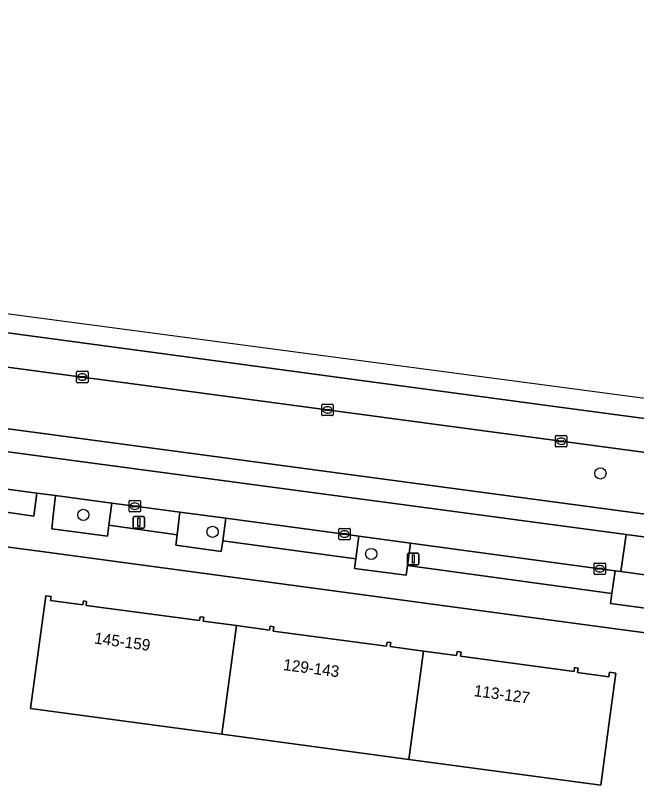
# Model space of a CAD drawing. Extents: x 161258 to 161838, y 380833 to 381727.
# Drawn here: x 161609.6 to 161663.8, y 381638.5 to 381706.2 of the extents above; entities that cross this region are included whole.
import ezdxf

# ---------------------------------------------------------------- set-up
doc = ezdxf.new("R2010")
doc.units = 0
for name, color, linetype in [('IMGEO_Berm_groen', 7, 'Continuous'), ('IMGEO_Boom', 7, 'Continuous'), ('IMGEO_Erf', 7, 'Continuous'), ('IMGEO_Groenvoorziening', 7, 'Continuous'), ('IMGEO_Kolk', 7, 'Continuous'), ('IMGEO_Lichtmast', 7, 'Continuous'), ('IMGEO_Pand', 7, 'Continuous'), ('IMGEO_Pand_nummerreeks', 7, 'Continuous'), ('IMGEO_Parkeervlak_halfverhard', 7, 'Continuous'), ('IMGEO_Parkeervlak_open', 7, 'Continuous'), ('IMGEO_Rijbaan_lokaal_open', 7, 'Continuous'), ('IMGEO_Rijbaan_regionaal_gesloten', 7, 'Continuous'), ('IMGEO_Voetpad_open', 7, 'Continuous')]:
    doc.layers.add(name, color=color, linetype=linetype)

msp = doc.modelspace()

# ---------------------------------------------------------------- linework, layer by layer
at = {"layer": 'IMGEO_Berm_groen'}
for points in [[(161419.518, 381699.804), (161598.175, 381675.897), (161597.877, 381673.07), (161595.231, 381672.953), (161593.354, 381672.734), (161591.581, 381672.404), (161665.053, 381662.56), (161687.397, 381659.556)], [(161679.007, 381666.04), (161677.666, 381666.255), (161657.266, 381668.988), (161618.127, 381674.239), (161615.451, 381674.598), (161596.053, 381677.191), (161575.643, 381679.932), (161555.208, 381682.652), (161534.802, 381685.416)]]:
    msp.add_lwpolyline(points, dxfattribs=at)
at = {"layer": 'IMGEO_Boom'}
for centre in [(161660.703, 381666.175), (161615.541, 381662.553), (161626.823, 381661.069), (161640.685, 381659.137)]:
    msp.add_circle(centre, 0.489, dxfattribs=at)
at = {"layer": 'IMGEO_Erf'}
msp.add_lwpolyline([(161744.895, 381638.467), (161745.302, 381641.497), (161740.472, 381642.131), (161716.743, 381645.239), (161684.01, 381649.696), (161663.105, 381652.447), (161611.247, 381659.449), (161599.202, 381661.023)], dxfattribs=at)
msp.add_lwpolyline([(161615.892, 381644.965), (161610.936, 381645.632), (161612.263, 381655.486), (161612.719, 381655.424), (161612.672, 381655.072), (161615.508, 381654.69), (161615.554, 381655.027), (161615.829, 381654.99), (161615.782, 381654.645), (161625.697, 381653.309), (161625.742, 381653.644), (161626.056, 381653.602), (161626.011, 381653.266), (161628.905, 381652.876), (161631.798, 381652.487), (161631.843, 381652.817), (161632.176, 381652.772), (161632.126, 381652.403), (161642.024, 381651.07), (161642.072, 381651.429), (161642.386, 381651.387), (161642.339, 381651.04), (161645.237, 381650.649), (161648.134, 381650.259), (161648.181, 381650.609), (161648.533, 381650.562), (161648.485, 381650.206), (161658.399, 381648.87), (161658.444, 381649.202), (161658.753, 381649.16), (161658.7, 381648.764), (161661.437, 381648.395), (161661.491, 381648.794), (161662.041, 381648.72), (161661.374, 381643.765), (161660.722, 381638.927), (161643.962, 381641.184), (161627.626, 381643.385)], close=True, dxfattribs=at)
at = {"layer": 'IMGEO_Groenvoorziening'}
for points in [[(161618.02, 381663.581), (161613.107, 381664.241), (161612.89, 381662.2), (161612.798, 381661.333), (161617.639, 381660.694), (161617.765, 381661.651)], [(161627.98, 381662.252), (161623.981, 381662.785), (161623.732, 381660.793), (161623.621, 381659.901), (161627.59, 381659.365), (161627.712, 381660.269)], [(161644.101, 381660.091), (161639.609, 381660.701), (161639.338, 381658.697), (161639.226, 381657.866), (161643.74, 381657.285), (161643.847, 381658.115)], [(161667.573, 381656.908), (161667.085, 381656.974), (161662.493, 381657.593), (161661.981, 381657.663), (161661.692, 381655.679), (161661.566, 381654.809), (161667.214, 381654.038), (161667.325, 381654.926)]]:
    msp.add_lwpolyline(points, close=True, dxfattribs=at)
at = {"layer": 'IMGEO_Kolk'}
for p, q in [((161614.95, 381674.17), (161614.95, 381675.022)), ((161615.025, 381675.096), (161615.877, 381675.096)), ((161615.438, 381674.876), (161615.463, 381674.876)), ((161615.951, 381675.022), (161615.951, 381674.17)), ((161615.877, 381674.096), (161615.025, 381674.096)), ((161615.209, 381674.59), (161615.209, 381674.602)), ((161615.647, 381674.553), (161615.249, 381674.553)), ((161615.252, 381674.639), (161615.65, 381674.639)), ((161615.461, 381674.316), (161615.436, 381674.316)), ((161615.693, 381674.602), (161615.693, 381674.59)), ((161636.358, 381671.299), (161636.358, 381672.151)), ((161636.433, 381672.225), (161637.285, 381672.225)), ((161636.846, 381672.005), (161636.871, 381672.005)), ((161637.359, 381672.151), (161637.359, 381671.299)), ((161636.617, 381671.719), (161636.617, 381671.731)), ((161637.055, 381671.682), (161636.657, 381671.682)), ((161636.66, 381671.768), (161637.058, 381671.768)), ((161636.869, 381671.445), (161636.844, 381671.445)), ((161637.101, 381671.731), (161637.101, 381671.719)), ((161637.285, 381671.225), (161636.433, 381671.225)), ((161656.765, 381668.561), (161656.765, 381669.413)), ((161656.84, 381669.487), (161657.692, 381669.487)), ((161657.766, 381669.413), (161657.766, 381668.561)), ((161657.024, 381668.981), (161657.024, 381668.993)), ((161657.462, 381668.944), (161657.064, 381668.944)), ((161657.067, 381669.03), (161657.465, 381669.03)), ((161657.276, 381668.707), (161657.251, 381668.707)), ((161657.253, 381669.267), (161657.278, 381669.267)), ((161657.508, 381668.993), (161657.508, 381668.981)), ((161657.692, 381668.487), (161656.84, 381668.487)), ((161619.532, 381662.884), (161619.532, 381663.736)), ((161619.607, 381663.81), (161620.459, 381663.81)), ((161619.791, 381663.304), (161619.791, 381663.316)), ((161620.229, 381663.267), (161619.831, 381663.267)), ((161619.834, 381663.353), (161620.232, 381663.353)), ((161620.02, 381663.59), (161620.045, 381663.59)), ((161620.275, 381663.316), (161620.275, 381663.304)), ((161620.533, 381663.736), (161620.533, 381662.884)), ((161620.459, 381662.81), (161619.607, 381662.81)), ((161620.043, 381663.03), (161620.018, 381663.03)), ((161637.851, 381660.446), (161637.851, 381661.298)), ((161637.926, 381661.372), (161638.778, 381661.372)), ((161638.339, 381661.152), (161638.364, 381661.152)), ((161638.852, 381661.298), (161638.852, 381660.446)), ((161638.11, 381660.866), (161638.11, 381660.878)), ((161638.548, 381660.829), (161638.15, 381660.829)), ((161638.153, 381660.915), (161638.551, 381660.915)), ((161638.362, 381660.592), (161638.337, 381660.592)), ((161638.594, 381660.878), (161638.594, 381660.866)), ((161638.778, 381660.372), (161637.926, 381660.372)), ((161660.143, 381657.417), (161660.143, 381658.269)), ((161660.218, 381658.343), (161661.07, 381658.343)), ((161660.402, 381657.837), (161660.402, 381657.849)), ((161660.84, 381657.8), (161660.442, 381657.8)), ((161660.445, 381657.886), (161660.843, 381657.886)), ((161660.631, 381658.123), (161660.656, 381658.123)), ((161660.886, 381657.849), (161660.886, 381657.837)), ((161661.144, 381658.269), (161661.144, 381657.417)), ((161661.07, 381657.343), (161660.218, 381657.343)), ((161660.654, 381657.563), (161660.629, 381657.563))]:
    msp.add_line(p, q, dxfattribs=at)
for points in [[(161614.95, 381674.17), (161614.95, 381675.022)], [(161615.025, 381675.096), (161615.877, 381675.096)], [(161615.951, 381675.022), (161615.951, 381674.17)], [(161615.877, 381674.096), (161615.025, 381674.096)], [(161636.358, 381671.299), (161636.358, 381672.151)], [(161636.433, 381672.225), (161637.285, 381672.225)], [(161637.359, 381672.151), (161637.359, 381671.299)], [(161637.285, 381671.225), (161636.433, 381671.225)], [(161656.765, 381668.561), (161656.765, 381669.413)], [(161656.84, 381669.487), (161657.692, 381669.487)], [(161657.766, 381669.413), (161657.766, 381668.561)], [(161657.692, 381668.487), (161656.84, 381668.487)], [(161619.532, 381662.884), (161619.532, 381663.736)], [(161619.607, 381663.81), (161620.459, 381663.81)], [(161620.533, 381663.736), (161620.533, 381662.884)], [(161620.459, 381662.81), (161619.607, 381662.81)], [(161637.851, 381660.446), (161637.851, 381661.298)], [(161637.926, 381661.372), (161638.778, 381661.372)], [(161638.852, 381661.298), (161638.852, 381660.446)], [(161638.778, 381660.372), (161637.926, 381660.372)], [(161660.143, 381657.417), (161660.143, 381658.269)], [(161660.218, 381658.343), (161661.07, 381658.343)], [(161661.144, 381658.269), (161661.144, 381657.417)], [(161661.07, 381657.343), (161660.218, 381657.343)]]:
    msp.add_lwpolyline(points, dxfattribs=at)
for centre, radius, start, end in [((161615.027, 381675.02), 0.0765, 91.55205, 178.44795), ((161615.027, 381675.02), 0.0765, 91.55205, 178.44795), ((161615.875, 381675.02), 0.0765, 1.55205, 88.44795), ((161615.875, 381675.02), 0.0765, 1.55205, 88.44795), ((161615.027, 381674.172), 0.0765, 181.55205, 268.44795), ((161615.027, 381674.172), 0.0765, 181.55205, 268.44795), ((161615.249, 381674.599), 0.0403, 85.87752, 175.75265), ((161615.246, 381674.589), 0.0366, 178.93798, 274.71019), ((161615.65, 381674.596), 0.043, 264.86636, 352.45326), ((161615.654, 381674.601), 0.0386, 1.73085, 96.63898), ((161615.875, 381674.172), 0.0765, 271.55205, 358.44795), ((161615.875, 381674.172), 0.0765, 271.55205, 358.44795), ((161636.435, 381672.149), 0.0765, 91.55205, 178.44795), ((161636.435, 381672.149), 0.0765, 91.55205, 178.44795), ((161637.283, 381672.149), 0.0765, 1.55205, 88.44795), ((161637.283, 381672.149), 0.0765, 1.55205, 88.44795), ((161636.657, 381671.728), 0.0403, 85.87752, 175.75265), ((161636.654, 381671.718), 0.0366, 178.93798, 274.71019), ((161637.058, 381671.725), 0.043, 264.86636, 352.45326), ((161637.062, 381671.73), 0.0386, 1.73085, 96.63898), ((161636.435, 381671.301), 0.0765, 181.55205, 268.44795), ((161636.435, 381671.301), 0.0765, 181.55205, 268.44795), ((161637.283, 381671.301), 0.0765, 271.55205, 358.44795), ((161637.283, 381671.301), 0.0765, 271.55205, 358.44795), ((161656.842, 381669.411), 0.0765, 91.55205, 178.44795), ((161656.842, 381669.411), 0.0765, 91.55205, 178.44795), ((161657.69, 381669.411), 0.0765, 1.55205, 88.44795), ((161657.69, 381669.411), 0.0765, 1.55205, 88.44795), ((161657.064, 381668.99), 0.0403, 85.87752, 175.75265), ((161657.061, 381668.98), 0.0366, 178.93798, 274.71019), ((161657.465, 381668.987), 0.043, 264.86636, 352.45326), ((161657.469, 381668.992), 0.0386, 1.73085, 96.63898), ((161656.842, 381668.563), 0.0765, 181.55205, 268.44795), ((161656.842, 381668.563), 0.0765, 181.55205, 268.44795), ((161657.69, 381668.563), 0.0765, 271.55205, 358.44795), ((161657.69, 381668.563), 0.0765, 271.55205, 358.44795), ((161619.609, 381663.734), 0.0765, 91.55205, 178.44795), ((161619.609, 381663.734), 0.0765, 91.55205, 178.44795), ((161619.831, 381663.313), 0.0403, 85.87752, 175.75265), ((161619.828, 381663.303), 0.0366, 178.93798, 274.71019), ((161620.232, 381663.31), 0.043, 264.86636, 352.45326), ((161620.236, 381663.315), 0.0386, 1.73085, 96.63898), ((161620.457, 381663.734), 0.0765, 1.55205, 88.44795), ((161620.457, 381663.734), 0.0765, 1.55205, 88.44795), ((161619.609, 381662.886), 0.0765, 181.55205, 268.44795), ((161619.609, 381662.886), 0.0765, 181.55205, 268.44795), ((161620.457, 381662.886), 0.0765, 271.55205, 358.44795), ((161620.457, 381662.886), 0.0765, 271.55205, 358.44795), ((161637.928, 381661.296), 0.0765, 91.55205, 178.44795), ((161637.928, 381661.296), 0.0765, 91.55205, 178.44795), ((161638.776, 381661.296), 0.0765, 1.55205, 88.44795), ((161638.776, 381661.296), 0.0765, 1.55205, 88.44795), ((161638.15, 381660.875), 0.0403, 85.87752, 175.75265), ((161638.147, 381660.865), 0.0366, 178.93798, 274.71019), ((161638.551, 381660.872), 0.043, 264.86636, 352.45326), ((161638.555, 381660.877), 0.0386, 1.73085, 96.63898), ((161637.928, 381660.448), 0.0765, 181.55205, 268.44795), ((161637.928, 381660.448), 0.0765, 181.55205, 268.44795), ((161638.776, 381660.448), 0.0765, 271.55205, 358.44795), ((161638.776, 381660.448), 0.0765, 271.55205, 358.44795), ((161660.22, 381658.267), 0.0765, 91.55205, 178.44795), ((161660.22, 381658.267), 0.0765, 91.55205, 178.44795), ((161660.442, 381657.846), 0.0403, 85.87752, 175.75265), ((161660.439, 381657.836), 0.0366, 178.93798, 274.71019), ((161660.843, 381657.843), 0.043, 264.86636, 352.45326), ((161660.847, 381657.848), 0.0386, 1.73085, 96.63898), ((161661.068, 381658.267), 0.0765, 1.55205, 88.44795), ((161661.068, 381658.267), 0.0765, 1.55205, 88.44795), ((161660.22, 381657.419), 0.0765, 181.55205, 268.44795), ((161660.22, 381657.419), 0.0765, 181.55205, 268.44795), ((161661.068, 381657.419), 0.0765, 271.55205, 358.44795), ((161661.068, 381657.419), 0.0765, 271.55205, 358.44795)]:
    msp.add_arc(centre, radius, start, end, dxfattribs=at)
for centre, major_axis, ratio, start_param, end_param in [((161615.437, 381674.596), (-0.387, 0.002), 0.722429, 4.712389, 7.853982), ((161615.462, 381674.596), (-0.39, 0.002), 0.717154, 1.570796, 4.712389), ((161636.845, 381671.725), (-0.387, 0.002), 0.722429, 4.712389, 7.853982), ((161636.87, 381671.725), (-0.39, 0.002), 0.717154, 1.570796, 4.712389), ((161657.252, 381668.987), (-0.387, 0.002), 0.722429, 4.712389, 7.853982), ((161657.277, 381668.987), (-0.39, 0.002), 0.717154, 1.570796, 4.712389), ((161620.019, 381663.31), (-0.387, 0.002), 0.722429, 4.712389, 7.853982), ((161620.044, 381663.31), (-0.39, 0.002), 0.717154, 1.570796, 4.712389), ((161638.338, 381660.872), (-0.387, 0.002), 0.722429, 4.712389, 7.853982), ((161638.363, 381660.872), (-0.39, 0.002), 0.717154, 1.570796, 4.712389), ((161660.63, 381657.843), (-0.387, 0.002), 0.722429, 4.712389, 7.853982), ((161660.655, 381657.843), (-0.39, 0.002), 0.717154, 1.570796, 4.712389)]:
    msp.add_ellipse(centre, major_axis=major_axis, ratio=ratio, start_param=start_param, end_param=end_param, dxfattribs=at)
at = {"layer": 'IMGEO_Lichtmast'}
for p, q in [((161619.893, 381661.502), (161619.893, 381662.302)), ((161619.893, 381662.302), (161619.893, 381661.502)), ((161619.993, 381662.402), (161620.783, 381662.402)), ((161620.783, 381662.402), (161619.993, 381662.402)), ((161620.883, 381662.302), (161620.883, 381661.502)), ((161620.883, 381661.502), (161620.883, 381662.302)), ((161620.783, 381661.402), (161619.993, 381661.402)), ((161619.993, 381661.402), (161620.783, 381661.402)), ((161643.954, 381659.197), (161644.744, 381659.197)), ((161644.744, 381659.197), (161643.954, 381659.197)), ((161643.854, 381658.297), (161643.854, 381659.097)), ((161643.854, 381659.097), (161643.854, 381658.297)), ((161644.844, 381659.097), (161644.844, 381658.297)), ((161644.844, 381658.297), (161644.844, 381659.097)), ((161644.744, 381658.197), (161643.954, 381658.197)), ((161643.954, 381658.197), (161644.744, 381658.197))]:
    msp.add_line(p, q, dxfattribs=at)
for points in [[(161620.313, 381662.277), (161620.463, 381662.277), (161620.463, 381661.527), (161620.313, 381661.527), (161620.313, 381662.277)], [(161644.274, 381659.072), (161644.424, 381659.072), (161644.424, 381658.322), (161644.274, 381658.322), (161644.274, 381659.072)]]:
    msp.add_lwpolyline(points, dxfattribs=at)
for centre, start, end in [((161619.993, 381662.302), 90, 180), ((161619.993, 381662.302), 90, 180), ((161620.783, 381662.302), 0, 90), ((161620.783, 381662.302), 360, 90), ((161619.993, 381661.502), 180, 270), ((161619.993, 381661.502), 180, 270), ((161620.783, 381661.502), 270, 0), ((161620.783, 381661.502), 270, 0), ((161643.954, 381659.097), 90, 180), ((161643.954, 381659.097), 90, 180), ((161644.744, 381659.097), 0, 90), ((161644.744, 381659.097), 360, 90), ((161643.954, 381658.297), 180, 270), ((161643.954, 381658.297), 180, 270), ((161644.744, 381658.297), 270, 0), ((161644.744, 381658.297), 270, 0)]:
    msp.add_arc(centre, 0.1, start, end, dxfattribs=at)
at = {"layer": 'IMGEO_Pand'}
for points in [[(161628.905, 381652.876), (161626.011, 381653.266), (161626.056, 381653.602), (161625.742, 381653.644), (161625.697, 381653.309), (161615.782, 381654.645), (161615.829, 381654.99), (161615.554, 381655.027), (161615.508, 381654.69), (161612.672, 381655.072), (161612.719, 381655.424), (161612.263, 381655.486), (161610.936, 381645.632), (161615.892, 381644.965), (161627.626, 381643.385)], [(161628.905, 381652.876), (161627.626, 381643.385), (161643.962, 381641.184), (161645.237, 381650.649), (161642.339, 381651.04), (161642.386, 381651.387), (161642.072, 381651.429), (161642.024, 381651.07), (161632.126, 381652.403), (161632.176, 381652.772), (161631.843, 381652.817), (161631.798, 381652.487)], [(161643.962, 381641.184), (161660.722, 381638.927), (161661.374, 381643.765), (161662.041, 381648.72), (161661.491, 381648.794), (161661.437, 381648.395), (161658.7, 381648.764), (161658.753, 381649.16), (161658.444, 381649.202), (161658.399, 381648.87), (161648.485, 381650.206), (161648.533, 381650.562), (161648.181, 381650.609), (161648.134, 381650.259), (161645.237, 381650.649)]]:
    msp.add_lwpolyline(points, close=True, dxfattribs=at)
at = {"layer": 'IMGEO_Parkeervlak_halfverhard'}
for points in [[(161591.581, 381672.404), (161591.138, 381672.463), (161591.126, 381672.369), (161590.884, 381670.486), (161662.932, 381660.822), (161667.513, 381660.211), (161687.091, 381657.568)], [(161687.397, 381659.556), (161665.053, 381662.56), (161591.581, 381672.404)]]:
    msp.add_lwpolyline(points, dxfattribs=at)
at = {"layer": 'IMGEO_Parkeervlak_open'}
for points in [[(161611.485, 381664.459), (161605.826, 381665.22), (161605.565, 381663.248), (161611.231, 381662.438)], [(161623.981, 381662.785), (161620.033, 381663.31), (161618.02, 381663.581), (161617.765, 381661.651), (161623.732, 381660.793)], [(161639.609, 381660.701), (161638.352, 381660.872), (161627.98, 381662.252), (161627.712, 381660.269), (161639.338, 381658.697)], [(161644.101, 381660.091), (161643.847, 381658.115), (161661.692, 381655.679), (161661.981, 381657.663), (161660.644, 381657.843)]]:
    msp.add_lwpolyline(points, close=True, dxfattribs=at)
at = {"layer": 'IMGEO_Rijbaan_lokaal_open'}
msp.add_lwpolyline([(161596.114, 381666.375), (161600.151, 381665.982), (161605.826, 381665.22), (161611.485, 381664.459), (161613.107, 381664.241), (161618.02, 381663.581), (161620.033, 381663.31), (161623.981, 381662.785), (161627.98, 381662.252), (161638.352, 381660.872), (161639.609, 381660.701), (161644.101, 381660.091), (161660.644, 381657.843), (161661.981, 381657.663), (161662.493, 381657.593), (161662.932, 381660.822), (161590.884, 381670.486)], dxfattribs=at)
msp.add_lwpolyline([(161667.513, 381660.211), (161662.932, 381660.822), (161662.493, 381657.593), (161667.085, 381656.974)], close=True, dxfattribs=at)
at = {"layer": 'IMGEO_Rijbaan_regionaal_gesloten'}
for points in [[(161736.137, 381662.69), (161719.327, 381665.313), (161716.253, 381665.701), (161712.371, 381666.274), (161708.386, 381666.804), (161704.351, 381667.34), (161702.189, 381667.689), (161690.967, 381669.187), (161665.691, 381672.562), (161583.995, 381683.424), (161565.314, 381685.907), (161412.782, 381706.187)], [(161412.591, 381704.741), (161412.495, 381704.012), (161412.199, 381701.786), (161413.286, 381701.641), (161433.673, 381698.93), (161474.493, 381693.446), (161493.724, 381690.885), (161500, 381690.051), (161514.402, 381688.138), (161534.802, 381685.416), (161555.208, 381682.652), (161575.643, 381679.932), (161596.053, 381677.191), (161615.451, 381674.598), (161618.127, 381674.239), (161657.266, 381668.988), (161677.666, 381666.255), (161679.007, 381666.04)], [(161723.875, 381661.551), (161719.934, 381662.085), (161715.913, 381662.59), (161711.965, 381663.118), (161707.95, 381663.655), (161704.447, 381664.184), (161700.839, 381664.728), (161696.656, 381665.513), (161692.816, 381666.233), (161688.805, 381667.074), (161684.795, 381667.916), (161680.859, 381668.646), (161668.901, 381670.395), (161656.473, 381672.064), (161640.688, 381674.185), (161624.53, 381676.356), (161612.423, 381677.982), (161592.223, 381680.696), (161572.343, 381683.367), (161560.228, 381684.995), (161544.014, 381687.173)], [(161544.014, 381687.173), (161560.228, 381684.995), (161572.343, 381683.367), (161592.223, 381680.696), (161612.423, 381677.982), (161624.53, 381676.356), (161640.688, 381674.185), (161656.473, 381672.064), (161668.901, 381670.395), (161680.859, 381668.646), (161684.795, 381667.916), (161688.805, 381667.074), (161692.816, 381666.233), (161696.656, 381665.513), (161700.839, 381664.728), (161704.447, 381664.184), (161707.95, 381663.655), (161711.965, 381663.118), (161715.913, 381662.59), (161719.934, 381662.085), (161723.875, 381661.551)]]:
    msp.add_lwpolyline(points, dxfattribs=at)
at = {"layer": 'IMGEO_Voetpad_open'}
for points in [[(161667.214, 381654.038), (161661.566, 381654.809), (161661.692, 381655.679), (161643.847, 381658.115), (161643.74, 381657.285), (161639.226, 381657.866), (161639.338, 381658.697), (161627.712, 381660.269), (161627.59, 381659.365), (161623.621, 381659.901), (161623.732, 381660.793), (161617.765, 381661.651), (161617.639, 381660.694), (161612.798, 381661.333), (161612.89, 381662.2), (161613.107, 381664.241), (161611.485, 381664.459), (161611.231, 381662.438), (161605.565, 381663.248)], [(161599.202, 381661.023), (161611.247, 381659.449), (161663.105, 381652.447), (161684.01, 381649.696), (161716.743, 381645.239), (161740.472, 381642.131), (161745.302, 381641.497), (161747.796, 381641.17), (161747.999, 381642.867)]]:
    msp.add_lwpolyline(points, dxfattribs=at)

# ---------------------------------------------------------------- texts
at = {"layer": 'IMGEO_Pand_nummerreeks'}
for s, rotation, p in [('145-159', 352.26198, (161616.453, 381651.316)), ('129-143', 352.56859, (161632.957, 381648.992)), ('113-127', 352.19169, (161649.604, 381646.722))]:
    msp.add_text(s, height=1, rotation=rotation, dxfattribs=at).set_placement(p)

doc.saveas('drawing.dxf')
